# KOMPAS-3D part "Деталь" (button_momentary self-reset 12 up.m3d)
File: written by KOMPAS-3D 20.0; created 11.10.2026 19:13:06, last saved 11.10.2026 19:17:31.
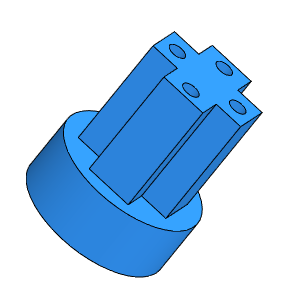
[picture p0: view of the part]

Document properties: Полное имя файла: D:\myProjects\Progect_esp32\box_compas\button_momentary self-reset 12 up.m3d

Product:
- Part/product: Деталь
    Масса: 0.00505493
  - Body: Тело 1
      Масса: 0.00126641

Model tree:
1. Эскиз:1
2. Элемент выдавливания:1
     Расстояние 1 = 5
3. Эскиз:2  (with: Элемент выдавливания:1)
4. Элемент выдавливания:2
     Расстояние 2 = 4
5. Эскиз:3  (with: Элемент выдавливания:1)
6. Элемент выдавливания:3
     Расстояние 1 = 10
7. Эскиз:4  (with: Элемент выдавливания:3)
8. Элемент выдавливания:4
     Расстояние 2 = 15
9. Массив по концентрической сетке:1  (with: Элемент выдавливания:4, Эскиз:4, Элемент выдавливания:1)  (4 pattern instances)
     Шаг 2 = 360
